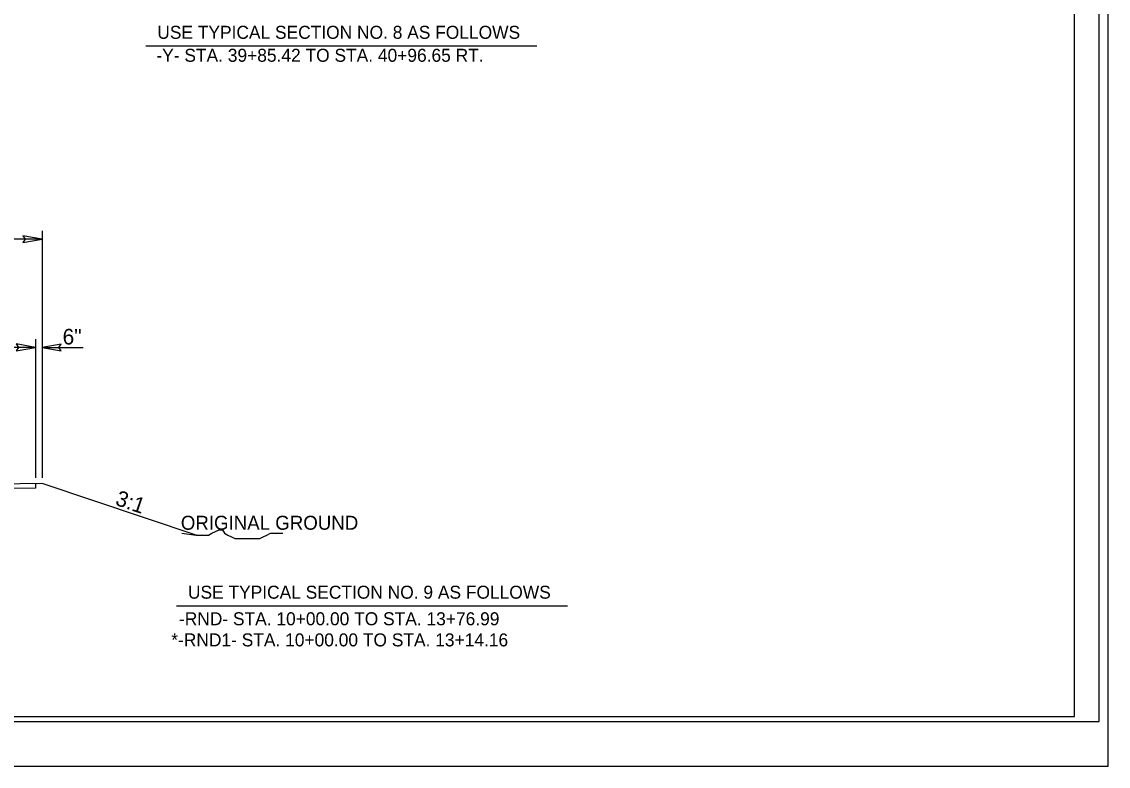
# Model space of a CAD drawing. Extents: x 958711 to 962106, y 831169 to 840840.
# Drawn here: x 959850 to 960395, y 836067 to 836440 of the extents above; entities that cross this region are included whole.
import ezdxf

# ---------------------------------------------------------------- set-up
doc = ezdxf.new("R2010")
doc.units = 0
for name, color, linetype in [('Old_Level_1', 7, 'Continuous'), ('Old_Level_11', 7, 'Continuous'), ('Old_Level_21', 7, 'Continuous'), ('Old_Level_3', 7, 'Continuous'), ('Sheet Plot Border Inside CELL', 7, 'Continuous'), ('Sheet Plot Border Outside CELL', 7, 'Continuous'), ('Sheet Typical CELL', 7, 'Continuous')]:
    doc.layers.add(name, color=color, linetype=linetype)

msp = doc.modelspace()

# ---------------------------------------------------------------- linework, layer by layer
at = {"layer": 'Old_Level_1'}
for p, q in [((959912.42, 836427.67), (960108.36, 836427.67)), ((959860.41, 836330.79), (959793.08, 836330.79)), ((959860.41, 836334.93), (959860.41, 836211.19)), ((959857.1, 836280.76), (959857.1, 836211.19)), ((959857.1, 836276.59), (959824.08, 836276.59)), ((959860.41, 836276.59), (959881.07, 836276.59)), ((959860.41, 836208.33), (959797.44, 836207.7)), ((959857.1, 836206.12), (959824.08, 836205.79)), ((959857.1, 836208.3), (959857.1, 836206.12)), ((959937.59, 836182.6), (959860.41, 836208.33)), ((959927.79, 836147.17), (960123.73, 836147.17))]:
    msp.add_line(p, q, dxfattribs=at)
at = {"layer": 'Old_Level_11'}
for points in [[(959850.8, 836329.13), (959860.41, 836330.79), (959850.75, 836332.5), (959851.97, 836330.79)], [(959847.5, 836274.94), (959857.1, 836276.59), (959847.44, 836278.3), (959848.67, 836276.59)], [(959870.01, 836278.25), (959860.41, 836276.59), (959870.07, 836274.88), (959868.84, 836276.59)]]:
    msp.add_lwpolyline(points, close=True, dxfattribs=at)
at = {"layer": 'Old_Level_21'}
msp.add_lwpolyline([(959930.5, 836183.48), (959937.59, 836182.6), (959939.37, 836182.6), (959942.03, 836182.6), (959943.8, 836182.6), (959945.57, 836183.48), (959947.35, 836184.38), (959949.12, 836185.26), (959950.9, 836185.26), (959951.79, 836183.48), (959953.56, 836182.6), (959955.33, 836181.7), (959957.1, 836180.83), (959958.88, 836180.83), (959960.65, 836180.83), (959962.43, 836180.83), (959964.2, 836180.83), (959965.97, 836180.83), (959967.74, 836180.83), (959969.52, 836180.83), (959971.29, 836181.7), (959973.06, 836182.6), (959974.83, 836183.48), (959977.5, 836183.48), (959979.27, 836183.48), (959981.05, 836183.48)], dxfattribs=at)
at = {"layer": 'Sheet Plot Border Inside CELL'}
msp.add_lwpolyline([(960390.3, 837144.29), (958723.8, 837144.29), (958723.8, 836089.19), (960390.3, 836089.19)], close=True, dxfattribs=at)
at = {"layer": 'Sheet Plot Border Outside CELL'}
msp.add_lwpolyline([(960394.8, 837166.74), (958710.8, 837166.74), (958710.8, 836066.74), (960394.8, 836066.74)], close=True, dxfattribs=at)
at = {"layer": 'Sheet Typical CELL'}
msp.add_lwpolyline([(960377.8, 837141.74), (958877.8, 837141.74), (958877.8, 836091.74), (960377.8, 836091.74)], close=True, dxfattribs=at)

# ---------------------------------------------------------------- texts
at = {"layer": 'Old_Level_1'}
for s, p in [('USE TYPICAL SECTION NO. 8 AS FOLLOWS', (959918.16, 836431.19)), ('-Y- STA. 39+85.42 TO STA. 40+96.65 RT.', (959917.72, 836419.68)), ('USE TYPICAL SECTION NO. 9 AS FOLLOWS', (959933.53, 836150.69)), ('-RND- STA. 10+00.00 TO STA. 13+76.99', (959929.03, 836137.38)), ('*-RND1- STA. 10+00.00 TO STA. 13+14.16', (959925.18, 836126.8))]:
    msp.add_text(s, height=6.5088, dxfattribs=at).set_placement(p)
at = {"layer": 'Old_Level_21'}
msp.add_text('ORIGINAL GROUND', height=7, dxfattribs=at).set_placement((959929.96, 836185.23))
at = {"layer": 'Old_Level_3'}
msp.add_text('6"', height=7.801, dxfattribs=at).set_placement((959870.72, 836278.07))
msp.add_text('3:1', height=7.801, rotation=341.0454, dxfattribs=at).set_placement((959896.65, 836197.83))

doc.saveas('drawing.dxf')
